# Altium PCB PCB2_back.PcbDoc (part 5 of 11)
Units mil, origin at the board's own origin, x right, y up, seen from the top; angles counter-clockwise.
Board outline 6299 x 3937 mil, 4 copper layers (TopLayer, GROUND, VCC, BottomLayer); 290 components, 470 nets, 2252 pads, 825 vias.
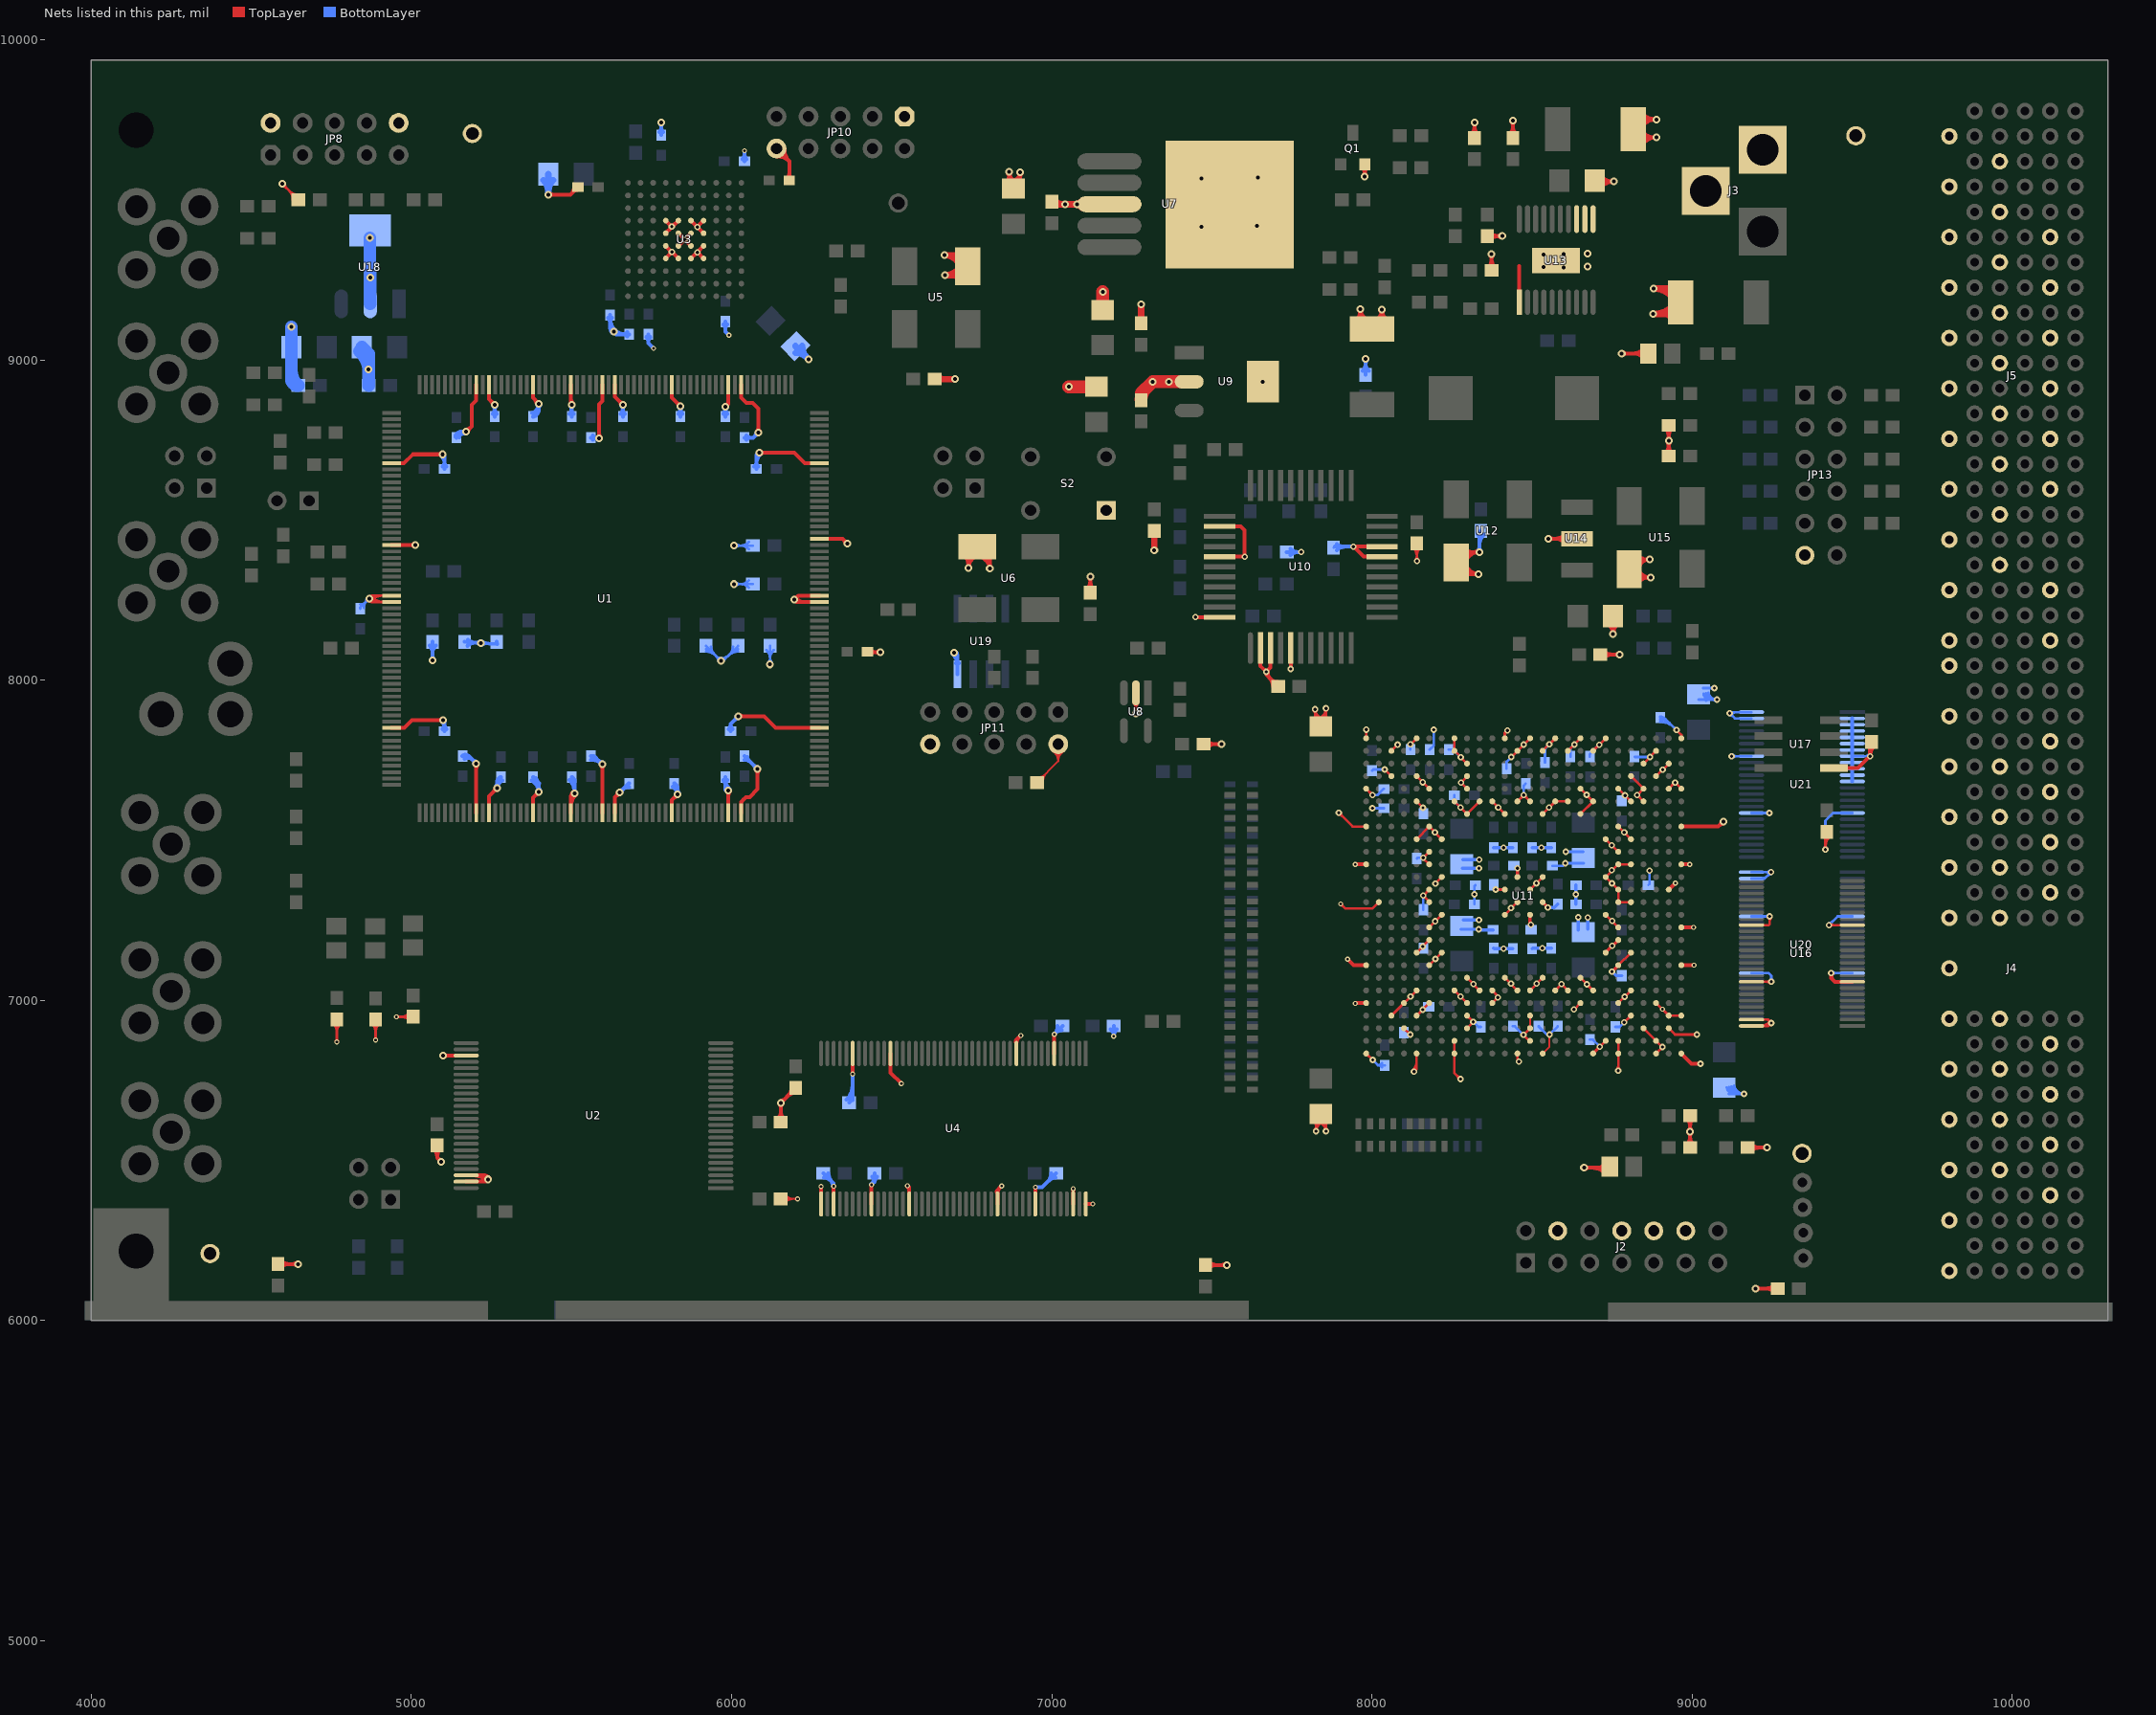
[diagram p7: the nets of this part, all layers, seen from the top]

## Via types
v1: diameter 16, hole 8, TopLayer to BottomLayer, 408 vias
v2: diameter 20, hole 10, TopLayer to BottomLayer, 221 vias
v3: diameter 24, hole 12, TopLayer to BottomLayer, 194 vias
v4: diameter 56.69, hole 56.69, TopLayer to BottomLayer, 2 vias

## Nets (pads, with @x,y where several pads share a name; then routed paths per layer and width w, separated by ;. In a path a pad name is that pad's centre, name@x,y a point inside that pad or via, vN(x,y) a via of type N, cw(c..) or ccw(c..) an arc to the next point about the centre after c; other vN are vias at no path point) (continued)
GND: C5.1 C6.1 C7.2 C8.1 C9.1 C10.2 C11.1 C12.2 C13.2 C14.2 C15.1 C16.1 C17.1 C18.1 C19.1 C20.2 C21.2 C22.1 C23.2 C27.1 C28.1 C29.2 C30.2 C31.2 C32.1 C33.1 C34.1 C35.2 C36.1 C37.1 C38.2 C39.1 C40.2 C41.1 C42.1 C43.2 C44.2 C45.2 C46.1 C47.2 C48.2 C49.2 C50.2 C51.2 C52.2 C53.2 C54.2 C55.2 C56.2 C57.2 C58.2 C59.1 C60.2 C61.2 C62.1 C63.2 C64.2 C65.1 C66.1 C67.2 C68.1 C69.2 C70.1 C71.2 C72.2 C73.2 C74.1 C75.2 C76.1 C77.2 C78.2 C79.1 C80.1 C81.1 C82.1 C83.1 C84.1 C86.1 C89.1 C91.2 C92.1 C93.2 C94.2 C95.2 C96.2 C97.2 C98.2 C99.2 C100.2 C101.2 C102.2 C103.2 C104.2 C105.1 C106.2 C107.2 C108.2 C109.2 C110.2 C111.2 C112.1 C113.2 C114.2 C115.2 C116.2 C117.1 C119.2 C120.2 C121.2 C122.2 C123.2 C124.2 C125.2 C126.2 C127.2 C128.2 C129.2 C130.1 C131.2 C132.2 C133.2 C134.2 C135.2 C136.2 C137.2 C138.2 C139.2 C140.2 C141.2 C142.2 C143.2 C144.2 C145.2 C146.2 C147.2 DS4.2 DS5.2 FB1.2 FB2.2 FB3.2 FB5.2 J2.4 J2.8 J2.10 J2.12 J3.2 J3.3 J4.B4 J4.B6 J4.B8 J4.B10 J4.B16 J4.B18 J4.B20 J4.B22 J4.D5 J4.D7 J4.D9 J4.D11 J4.D15 J4.D17 J4.D19 J4.D21 J4.F1 J4.F3 J4.F5 J4.F7 J4.F9 J4.F11 J4.F13 J4.F15 J4.F17 J4.F19 J4.F21 J4.F23 J4.F25 J5.B1 J5.B3 J5.B7 J5.B9 J5.B11 J5.B13 J5.B15 J5.B17 J5.D4 J5.D6 J5.D8 J5.D10 J5.D12 J5.D14 J5.D16 J5.D18 J5.D20 J5.F1 J5.F3 J5.F5 J5.F7 J5.F9 J5.F11 J5.F13 J5.F15 J5.F17 J5.F19 J5.F21 JP8.2 JP8.10 JP10.1 JP10.10 JP11.2 JP11.10 JP13.11 pad.5 pad.6 pad.7 pad.8 Q1.3 R4.2 R14.1 R16.2 R17.2 R20.1 R25.1 R43.2 R48.1 R50.1 R52.1 R53.1 R55.1 R67.1 R68.1 S2.1 U1.10 U1.30 U1.31 U1.40 U1.52 U1.69 U1.71 U1.80 U1.89 U1.91 U1.96 U1.102 U1.109 U1.111 U1.129 U1.142 U1.150 U1.151 U1.171 U1.190 U1.192 U1.199 U1.205 U1.210 U1.212 U1.221 U1.230 U1.232 U2.27 U2.46 U2.47 U3.D4 U3.D5 U3.D6 U3.D7 U3.E4 U3.E5 U3.E6 U3.E7 U3.F4 U3.F5 U3.F6 U3.F7 U3.G4 U3.G5 U3.G6 U3.G7 U4.6 U4.12 U4.32 U4.38 U4.44 U4.46 U4.52 U4.58 U4.72 U4.78 U4.84 U4.86 U5.2 U6.2 U7.3 U8.2 U9.2 U9.4 U10.2 U10.3 U10.5 U10.18 U10.19 U10.35 U10.38 U10.44 U11.A1 U11.A3 U11.A6 U11.A8 U11.A12 U11.A14 U11.A19 U11.A22 U11.A26 U11.AA4 U11.AA5 U11.AA8 U11.AA10 U11.AA11 U11.AA13 U11.AA14 U11.AA16 U11.AA17 U11.AA19 U11.AA22 U11.AB1 U11.AB2 U11.AB4 U11.AB6 U11.AB9 U11.AB18 U11.AB21 U11.AB26 U11.AC3 U11.AC5 U11.AC18 U11.AC22 U11.AC24 U11.AD2 U11.AD4 U11.AD18 U11.AE3 U11.AE8 U11.AE10 U11.AE12 U11.AE14 U11.AE19 U11.AE24 U11.AF1 U11.AF7 U11.AF9 U11.AF11 U11.AF13 U11.AF15 U11.AF19 U11.AF22 U11.AF26 U11.B3 U11.B6 U11.B7 U11.B13 U11.B19 U11.C2 U11.C4 U11.C13 U11.C18 U11.C23 U11.D1 U11.D2 U11.D5 U11.D13 U11.D18 U11.D22 U11.D24 U11.E3 U11.E6 U11.E9 U11.E16 U11.E18 U11.E21 U11.E23 U11.E26 U11.F5 U11.F8 U11.F10 U11.F11 U11.F13 U11.F14 U11.F16 U11.F17 U11.F19 U11.F22 U11.G9 U11.G12 U11.G15 U11.G18 U11.H1 U11.H6 U11.H21 U11.H26 U11.J5 U11.J7 U11.J20 U11.J22 U11.K6 U11.K21 U11.L1 U11.L6 U11.L21 U11.M7 U11.M13 U11.M15 U11.M20 U11.N5 U11.N6 U11.N12 U11.N14 U11.N21 U11.N25 U11.P2 U11.P6 U11.P13 U11.P15 U11.P21 U11.R7 U11.R12 U11.R14 U11.R20 U11.T1 U11.T5 U11.T6 U11.T21 U11.T26 U11.U6 U11.U21 U11.V5 U11.V7 U11.V20 U11.V22 U11.W1 U11.W6 U11.W21 U11.W26 U11.Y9 U11.Y12 U11.Y15 U11.Y18 U12.2 U13.1 U13.11 U13.12 U13.13 U14.2 U15.2 U16.8 U16.17 U16.32 U16.41 U16.47 U16.48 U17.5 U18.2 U18.4 U19.4 U20.8 U20.17 U20.32 U20.41 U20.47 U20.48 U21.2 U21.3 U21.4 U21.5 U21.6 U21.7 U21.8 U21.9 U21.10 U21.11 U21.12 U21.17 U21.32 U21.41 U21.47 U21.48 | length 33831
  TopLayer w6: R20.1@6153.46,6380 v1(6206,6380) ; R20.1@6162.99,6372.44 cw(c6181.23,6354.2) 6181.23,6380 cw(c6181.23,6405.8) R20.1@6162.99,6387.56 ; R20.1@6167.23,6368.2 cw(c6195.71,6339.72) 6195.71,6380 cw(c6195.71,6420.28) R20.1@6167.23,6391.8 ; v1@6202.46,6376.46 ccw(c6193.93,6367.93) 6193.93,6380 ccw(c6193.93,6392.07) v1@6202.46,6383.54 ; R25.1@6953.46,7680 7020,7746.54 ; R25.1@6955.43,7690.69 ccw(c6955.43,7711.73) R25.1@6970.31,7696.85 ; R25.1@6955.43,7696.69 ccw(c6955.43,7732.21) 6980.56,7707.09 ; R25.1@6966.12,7680 cw(c6996.67,7680) 6975.07,7701.6 ; R25.1@6972.12,7680 cw(c7017.15,7680) 6985.31,7711.84 ; JP11.2@7004.05,7776.98 cw(c6982.96,7746.54) 7020,7746.54 ; JP11.2@7007.47,7781.92 cw(c6990.9,7757.99) 7020,7757.99 cw(c7049.1,7757.99) JP11.2@7032.53,7781.92 ; JP11.2@7020,7800 7020,7746.54 ; JP11.2@7035.95,7776.98 ccw(c7057.04,7746.54) 7020,7746.54 ; U11.C13@8493.56,6912.74 U11.D13@8493.56,6952.11 ; U11.A12@8532.93,6834 8553.99,6855.06 v2(8553.99,6893)
  TopLayer w8: v3@4596.54,9542 cw(c4596.54,9522.69) 4610.19,9536.34 cw(c4623.85,9550) v3@4604.54,9550 ; v3(4596.54,9550) R14.1@4646.54,9500 ; 4616.4,9530.14 cw(c4586.26,9500) R14.1@4628.88,9500 ; 4621.15,9525.38 ccw(c4644.57,9548.8) R14.1@4644.57,9515.68 ; R14.1@4630.06,9516.48 cw(c4613.58,9500) R14.1@4636.88,9500 ; R4.2@4755.91,6927.48 cw(c4729.13,6900.7) 4767,6900.7 cw(c4804.87,6900.7) R4.2@4778.09,6927.48 ; v1@4764.17,6872.83 ccw(c4757.34,6879.66) 4767,6879.66 ccw(c4776.66,6879.66) v1@4769.83,6872.83 ; v1(4767,6870) R4.2@4767,6940.54 ; v3@4862.34,8249.34 ccw(c4874.86,8261.86) 4874.86,8244.16 ; v3@4869.4,8247.12 cw(c4871.28,8236.6) 4878.84,8244.16 ; v3@4870.76,8262.51 ccw(c4872.76,8267.92) 4876.84,8263.84 ; v3@4873.66,8249.34 cw(c4908.66,8214.34) U1.150@4908.66,8263.84 ; v3@4873.66,8260.66 ccw(c4913.49,8300.49) U1.151@4913.49,8244.16 ; v3@4875.51,8257.76 cw(c4880.92,8259.76) 4876.84,8263.84 ; v3@4875.88,8253.6 ccw(c4886.4,8251.72) 4878.84,8244.16 ; R16.2@4876.91,6926.48 cw(c4850.13,6899.7) 4888,6899.7 cw(c4925.87,6899.7) R16.2@4899.09,6926.48 ; v1@4885.17,6878.83 ccw(c4878.34,6885.66) 4888,6885.66 ccw(c4897.66,6885.66) v1@4890.83,6878.83 ; v1(4888,6876) R16.2@4888,6939.54 ; 4889.35,8263.84 ccw(c4889.35,8233.65) v3(4868,8255) ; 4894.18,8244.16 cw(c4894.18,8281.18) v3(4868,8255) ; U1.151@4937.69,8244.16 4878.84,8244.16 ; U1.150@4937.69,8263.84 4876.84,8263.84 ; v1(4952.54,6948.54) R17.2@5005,6948.54 ; v1@4955.36,6945.71 cw(c4962.19,6938.88) 4962.19,6948.54 cw(c4962.19,6958.19) v1@4955.36,6951.36 ; R17.2@4993.91,6937.44 ccw(c4967.13,6910.67) 4967.13,6948.54 ccw(c4967.13,6986.4) R17.2@4993.91,6959.63 ; C20.2@7816.62,6625.44 cw(c7796.39,6605.21) 7825,6605.21 ; C21.2@7816.62,7874.56 ccw(c7803.63,7887.55) 7822,7887.55 ; v2@7817.76,7904.76 cw(c7807.51,7894.51) 7822,7894.51 cw(c7836.49,7894.51) v2@7826.24,7904.76 ; v2@7820.76,6595.24 ccw(c7810.51,6605.49) 7825,6605.49 ccw(c7839.49,6605.49) v2@7829.24,6595.24 ; C21.2@7822,7855 v2(7822,7909) ccw(c7850.21,7909) C21.2@7843.05,7881.71 ; 7822,7888.25 ccw(c7844.76,7888.25) C21.2@7838.98,7866.24 ; 7822,7898.63 ccw(c7847.49,7898.63) C21.2@7841.01,7873.97 ; v2@7825,6589.88 cw(c7856.01,6589.88) C20.2@7845.44,6619.03 ; v2(7825,6591) C20.2@7825,6639 ; 7825,6601.29 cw(c7851.87,6601.29) C20.2@7842.71,6626.55 ; 7825,6612.7 cw(c7847.74,6612.7) C20.2@7839.98,6634.07 ; C21.2@7834.37,7880.9 ccw(c7822.82,7912) v2(7856,7912) C21.2@7856,7851 ; C20.2@7835.09,6618.85 cw(c7825.18,6589.67) v2@7856,6589.67 ; C21.2@7837.15,7873.4 ccw(c7827.09,7900.5) 7856,7900.5 ; C20.2@7837.67,6626.42 cw(c7828.98,6600.83) v2@7856,6600.83 ; C21.2@7839.94,7865.9 ccw(c7831.36,7888.99) 7856,7888.99 ; C20.2@7840.24,6634 cw(c7832.77,6612) 7856,6612 ; v2@7851.76,6595.24 ccw(c7841.51,6605.49) 7856,6605.49 ccw(c7870.49,6605.49) v2@7860.24,6595.24 ; v2@7851.76,7907.76 cw(c7841.51,7897.51) 7856,7897.51 cw(c7870.49,7897.51) v2@7860.24,7907.76 ; v2(7856,6591) C20.2@7856,6644 ; 7856,6607.62 cw(c7881.2,6607.62) C20.2@7863.38,6625.44 ; 7856,7892.38 ccw(c7881.2,7892.38) C21.2@7863.38,7874.56 ; v2@7896,7580 cw(c7896,7565.51) 7906.24,7575.76 cw(c7916.49,7586) v2@7902,7586 ; v2(7896,7586) 7939.34,7542.66 U11.W26@7981.75,7542.66 ; v1@7902,7297 cw(c7902,7287.34) 7908.83,7294.17 cw(c7915.66,7301) v1@7906,7301 ; v1(7902,7301) 7916,7287 8001.68,7287 U11.N25@8021.12,7306.44 ; U11.A26@7981.75,6834 v2(8002,6813.75) ; U11.AB26@7981.75,7660.77 v2(8001.52,7641) ; U11.AF26@7981.75,7818.25 v2(7981.75,7845.25) ; v2(8039.63,7721) U11.AC24@8060.49,7700.14 ; U11.D24@8060.49,6952.11 U11.F22@8139.23,7030.85 ; U11.AE24@8060.49,7778.88 v2(8080,7798.39) ; U11.C23@8099.86,6912.74 v2(8119.6,6893) ; v2(8120,7799.02) U11.AF22@8139.23,7818.25 ; v2@8126.76,6781.24 ccw(c8096.65,6811.35) 8139.23,6811.35 ; R43.2@8128.91,8413.48 cw(c8102.13,8386.7) 8140,8386.7 cw(c8177.87,8386.7) R43.2@8151.09,8413.48 ; v2(8131,6777) 8139.23,6785.23 ; v2@8132,6782.92 ccw(c8133.37,6791.08) 8139.23,6785.23 ; v2@8132.41,6775.59 ccw(c8115.96,6792.04) 8139.23,6792.04 ; v2@8135.76,8376.24 ccw(c8125.51,8386.49) 8140,8386.49 ccw(c8154.49,8386.49) v2@8144.24,8376.24 ; v2@8136.92,6778 cw(c8145.08,6779.37) 8139.23,6785.23 ; U11.A22@8139.23,6834 8139.23,6785.23 ; U11.D22@8139.23,6952.11 U11.E21@8178.6,6991.48 ; U11.J22@8139.23,7148.96 U11.K21@8178.6,7188.33 ; U11.V22@8139.23,7503.29 U11.W21@8178.6,7542.66 U11.V20@8217.97,7503.29 ; U11.AA22@8139.23,7621.4 v2(8159,7601.63) ; U11.AC22@8139.23,7700.14 U11.AB21@8178.6,7660.77 ; v2(8140,8372) R43.2@8140,8426.54 ; U11.H21@8178.6,7109.59 U11.J20@8217.97,7148.96 ; U11.L21@8178.6,7227.7 U11.M20@8217.97,7267.07 ; U11.N21@8178.6,7306.44 8178.6,7308.4 v2(8160,7327) 8178.6,7345.6 U11.P21@8178.6,7345.81 ; U11.T21@8178.6,7424.55 8159.68,7443.47 v2(8159.68,7445) U11.U21@8178.6,7463.92 ; v2(8197.79,7365) U11.R20@8217.97,7385.18 ; U11.B19@8257.34,6873.37 8257.34,6772.66 v2(8276,6754) ; U11.F19@8257.34,7030.85 U11.E18@8296.71,6991.48 ; U11.AA19@8257.34,7621.4 U11.Y18@8296.71,7582.03 U11.AA17@8336.08,7621.4 ; U11.AF19@8257.34,7818.25 U11.AE19@8257.34,7778.88 U11.AD18@8296.71,7739.51 ; v2@8270,6754 ccw(c8255.51,6754) 8265.76,6764.24 ccw(c8276,6774.49) v2@8276,6760 ; U11.C18@8296.71,6912.74 8316,6932.03 v2(8316,6932.82) U11.D18@8296.71,6952.11 ; U11.G18@8296.71,7070.22 U11.F17@8336.08,7030.85 ; U11.AB18@8296.71,7660.77 8278,7679.48 v2(8278,7680) 8296.71,7698.71 U11.AC18@8296.71,7700.14 ; U11.E16@8375.45,6991.48 v2(8393,7009.03) 8393,7013.3 U11.F16@8375.45,7030.85 ; U11.AA16@8375.45,7621.4 U11.Y15@8414.82,7582.03 ; U11.G15@8414.82,7070.22 U11.F14@8454.19,7030.85 ; U11.M15@8414.82,7267.07 U11.N14@8454.19,7306.44 ; U11.AF15@8414.82,7818.25 8414.82,7834.82 v2(8423,7843) ; v2(8435,7759.69) v2(8473.88,7798.58) U11.AF13@8493.56,7818.25 ; U11.A14@8454.19,6834 8454.19,6813.81 v2(8459,6809) ; U11.AA14@8454.19,7621.4 v2(8473.79,7641) 8473.96,7641 U11.AA13@8493.56,7621.4 ; U11.B13@8493.56,6873.37 8491.45,6873.37 v2(8472.82,6892) U11.C13@8493.56,6912.74 ; U11.F13@8493.56,7030.85 U11.G12@8532.93,7070.22 ; U11.P13@8493.56,7345.81 U11.R12@8532.93,7385.18 ; U11.Y12@8532.93,7582.03 U11.AA11@8572.3,7621.4 U11.AA10@8611.67,7621.4 ; U11.AE12@8532.93,7778.88 U11.AF11@8572.3,7818.25 ; U11.F11@8572.3,7030.85 8591.52,7050.07 v2(8591.52,7051) U11.F10@8611.67,7030.85 ; U11.AE10@8611.67,7778.88 U11.AF9@8651.04,7818.25 ; v2(8631,6971.44) U11.E9@8651.04,6991.48 ; U11.G9@8651.04,7070.22 U11.F8@8690.41,7030.85 ; U11.Y9@8651.04,7582.03 U11.AA8@8690.41,7621.4 U11.AB9@8651.04,7660.77 ; U11.A8@8690.41,6834 U11.B7@8729.78,6873.37 ; U11.AE8@8690.41,7778.88 U11.AF7@8729.78,7818.25 ; U11.M7@8729.78,7267.07 U11.L6@8769.15,7227.7 ; U11.V7@8729.78,7503.29 U11.U6@8769.15,7463.92 ; v2@8764.76,6784.24 ccw(c8754.15,6794.85) 8769.15,6794.85 ; v2(8769,6780) 8769.15,6780.15 U11.B6@8769.15,6873.37 ; 8769.15,6794.12 ccw(c8783.12,6794.12) v2@8773.24,6784.24 ; U11.E6@8769.15,6991.48 U11.F5@8808.52,7030.85 ; U11.H6@8769.15,7109.59 U11.J5@8808.52,7148.96 ; U11.W6@8769.15,7542.66 U11.V5@8808.52,7503.29 ; U11.AB6@8769.15,7660.77 U11.AA5@8808.52,7621.4 ; v2(8787.41,6931) U11.D5@8808.52,6952.11 ; U11.N5@8808.52,7306.44 U11.N6@8769.15,7306.44 U11.P6@8769.15,7345.81 U11.R7@8729.78,7385.18 U11.T6@8769.15,7424.55 U11.T5@8808.52,7424.55 ; U11.AC5@8808.52,7700.14 U11.AB4@8847.89,7660.77 v2(8828.12,7641) 8828,7641 8847.6,7621.4 U11.AA4@8847.89,7621.4 ; U11.C4@8847.89,6912.74 8906.63,6854 v2(8907.26,6854) U11.A3@8887.26,6834 ; U11.AD4@8847.89,7739.51 U11.AE3@8887.26,7778.88 ; U11.E3@8887.26,6991.48 U11.D2@8926.63,6952.11 U11.D1@8966,6952.11 ; U11.AC3@8887.26,7700.14 U11.AD2@8926.63,7739.51 ; U11.C2@8926.63,6912.74 8946.37,6893 v2(9015,6893) ; U11.AB2@8926.63,7660.77 8945.86,7680 v2(8946.77,7680) U11.AB1@8966,7660.77 ; v2(8951,7844) 8966,7829 U11.AF1@8966,7818.25 ; v2@9010.76,6888.76 ccw(c9000.51,6878.51) 9000.51,6893 ccw(c9000.51,6907.49) v2@9010.76,6897.24 ; U16.48@9185.04,6920 9238,6920 ; U16.47@9185.04,6939.69 9236.32,6939.69 v2(9247,6929) 9238,6920 ; U16.41@9185.04,7057.8 v2(9247.2,7057.8) ; U16.32@9185.04,7234.96 9238.96,7234.96 9242.2,7238.2 v2(9242.2,7262.2) ; U16.48@9210.79,6920 ccw(c9210.79,6965.21) v2@9242.76,6933.24 ; 9230.1,6920 ccw(c9230.1,6945.9) v2@9248.41,6927.59 ; v2@9237.96,7257.96 cw(c9227.72,7247.72) 9242.2,7247.72 cw(c9256.69,7247.72) v2@9246.45,7257.96 ; v2@9241,6929 ccw(c9226.51,6929) 9236.76,6939.24 ccw(c9247,6949.49) v2@9247,6935 ; v2@9241.03,6928.43 cw(c9230.58,6927.42) 9238,6920 ; v2@9242.96,7053.55 ccw(c9232.72,7043.31) 9232.72,7057.8 ccw(c9232.72,7072.28) v2@9242.96,7062.04 ; v2@9246.43,6923.03 ccw(c9245.42,6912.58) 9238,6920 ; C36.1@9408.91,7513.48 cw(c9391.79,7496.36) 9416,7496.36 cw(c9448.21,7496.36) C36.1@9425.43,7519.13 ; v2@9411.76,7475.24 ccw(c9401.51,7485.49) 9416,7485.49 ccw(c9430.49,7485.49) v2@9420.24,7475.24 ; v2(9416,7471) 9416,7522.54 C36.1@9420,7526.54 ; v2@9416,7477.04 cw(c9467.52,7477.04) C36.1@9431.09,7513.48 ; v2(9427.04,7234.96) U16.17@9500,7234.96 ; v2@9431.28,7230.72 cw(c9441.53,7220.47) 9441.53,7234.96 cw(c9441.53,7249.45) v2@9431.28,7239.2 ; v3(4868,8255) 4876.84,8263.84 ; v3(4868,8255) 4878.84,8244.16
  TopLayer w10: v2(8386.19,7345.81) U11.P15@8414.82,7345.81 ; U11.R14@8454.19,7385.18 v2(8454.19,7412.19) ; U11.M13@8493.56,7267.07 8493.56,7238.44 v2(8496,7236) ; U11.N12@8532.93,7306.44 v2(8549.37,7290) ; U11.J7@8729.78,7148.96 U11.K6@8769.15,7188.33 ; v2(8749.56,7090) U11.H6@8769.15,7109.59
  TopLayer w12: FB1.2@4583,6176.46 v3(4645.46,6176.46) ; FB1.2@4592.68,6166.79 cw(c4616.04,6143.43) 4616.04,6176.46 cw(c4616.04,6209.5) FB1.2@4592.68,6186.14 ; v3@4641.22,6172.22 ccw(c4630.98,6161.98) 4630.98,6176.46 ccw(c4630.98,6190.95) v3@4641.22,6180.71 ; U1.171@4937.69,7850.46 4977.46,7850.46 5002,7875 v3(5099,7875) ; U1.142@4937.69,8421.32 v3(5012.32,8421.32) ; U1.129@4937.69,8677.23 4976.23,8677.23 5004,8705 v3(5097,8705) ; v3@5008.08,8417.08 ccw(c4997.84,8406.84) 4997.84,8421.32 ccw(c4997.84,8435.81) v3@5008.08,8425.57 ; C5.1@5070.32,6534.89 cw(c5046.96,6511.53) 5080,6511.53 cw(c5113.04,6511.53) C5.1@5089.68,6534.89 ; C5.1@5080,6546.54 5080,6509 v3(5093,6496) ; v3@5087,6496 ccw(c5072.51,6496) 5082.76,6506.24 ccw(c5093,6516.49) v3@5093,6502 ; v3@5092.76,8700.76 ccw(c5082.51,8690.51) 5082.51,8705 ccw(c5082.51,8719.49) v3@5092.76,8709.24 ; v3@5094.76,7870.76 ccw(c5084.51,7860.51) 5084.51,7875 ccw(c5084.51,7889.49) v3@5094.76,7879.24 ; v3(5098,6827) U2.27@5170.72,6827.39 ; v3@5102.22,6831.27 ccw(c5112.41,6841.56) 5112.49,6827.08 ccw(c5112.56,6812.59) v3@5102.27,6822.78 ; U2.47@5170.72,6433.69 5231.69,6433.69 v3(5239,6441) 5226.63,6453.37 U2.46@5170.72,6453.37 ; v3(5171,8776) 5188,8793 5188,8859 5202.46,8873.46 U1.111@5202.46,8922.31 ; v3@5171,8782 ccw(c5171,8796.49) 5181.24,8786.24 ccw(c5191.49,8776) v3@5177,8776 ; U2.46@5194.65,6453.37 cw(c5194.65,6396.65) v3@5234.76,6436.76 ; v3@5198.21,7735.3 cw(c5187.97,7725.06) 5202.46,7725.06 cw(c5216.94,7725.06) v3@5206.7,7735.3 ; U1.190@5202.46,7585.69 v3(5202.46,7739.54) ; U2.47@5206.85,6433.69 ccw(c5206.85,6473.15) v3@5234.76,6445.24 ; 5223.62,6453.37 cw(c5223.62,6425.62) v3@5243.24,6445.24 ; v3@5233,6441 ccw(c5218.51,6441) 5228.76,6451.24 ccw(c5239,6461.49) v3@5239,6447 ; U1.192@5241.83,7585.69 5241.83,7637.83 v3(5267,7663) ; U1.109@5241.83,8922.31 5241.83,8877.17 v3(5260,8859) ; v3@5254,8859 ccw(c5239.51,8859) 5249.76,8869.24 ccw(c5260,8879.49) v3@5260,8865 ; v3@5261,7663 cw(c5246.51,7663) 5256.76,7652.76 cw(c5267,7642.51) v3@5267,7657 ; U1.199@5379.62,7585.69 5379.62,7632.62 v3(5398,7651) ; U1.102@5379.62,8922.31 5379.62,8881.38 v3@5398,8863 ; 5385.34,8875.66 cw(c5371.69,8862) v3@5391,8862 ; v3@5392,7651 cw(c5377.51,7651) 5387.76,7640.76 cw(c5398,7630.51) v3@5398,7645 ; v3(5427.2,9516.2) 5496.2,9516.2 C6.1@5520,9540 ; v3@5431.44,9511.95 cw(c5441.68,9501.71) 5441.68,9516.2 cw(c5441.68,9530.68) v3@5431.44,9520.44 ; U1.205@5497.73,7585.69 5497.73,7634.73 v3(5509,7646) ; U1.205@5497.73,7604.31 cw(c5550.69,7604.31) v3@5513.24,7641.76 ; 5497.73,7633.28 cw(c5521.72,7633.28) v3@5504.76,7650.24 ; 5497.73,8879.96 ccw(c5519.96,8879.96) v3@5504.24,8864.24 ; U1.96@5497.73,8922.31 5497.73,8862.27 v3(5500,8860) ; 5500.37,9520.37 ccw(c5480.74,9540) C6.1@5508.5,9540 ; v3@5503,7646 cw(c5488.51,7646) 5498.76,7635.76 cw(c5509,7625.51) v3@5509,7640 ; C6.1@5506.4,9526.4 cw(c5517.5,9515.31) C6.1@5517.5,9531 ; v3@5581.76,8759.24 ccw(c5571.51,8769.49) 5586,8769.49 ccw(c5600.49,8769.49) v3@5590.24,8759.24 ; v3(5586,8755) 5586,8861 5596.16,8871.16 U1.91@5596.16,8922.31 ; v3@5591.91,7732.6 cw(c5581.67,7722.36) 5596.16,7722.36 cw(c5610.64,7722.36) v3@5600.4,7732.6 ; U1.210@5596.16,7585.69 v3(5596.16,7736.84) ; U1.212@5635.53,7585.69 5635.53,7634.53 v3(5650,7649) ; U1.89@5635.53,8922.31 5635.53,8884.47 v3(5660,8860) ; v3@5644,7649 cw(c5629.51,7649) 5639.76,7638.76 cw(c5650,7628.51) v3@5650,7643 ; v3@5654,8860 ccw(c5639.51,8860) 5649.76,8870.24 ccw(c5660,8880.49) v3@5660,8866 ; U3.G4@5794.11,9316.78 5813.73,9336.4 v2@5813.73,9336.53 ; U3.F4@5794.11,9356.15 U3.G5@5833.48,9316.78 ; U3.E4@5794.11,9395.52 5813.8,9415.2 U3.D5@5833.48,9434.89 ; U3.D4@5794.11,9434.89 v2(5813.05,9415.95) ; 5805.16,9406.57 ccw(c5795.78,9415.95) v2@5809.05,9415.95 ; 5805.53,9328.19 ccw(c5796.66,9337.06) v2@5809.2,9337.06 ; U1.221@5812.69,7585.69 5812.69,7624.69 v3(5831,7643) ; U1.80@5812.69,8922.31 5812.69,8882.31 v3(5840,8855) ; v2@5813.05,9419.95 ccw(c5813.05,9433.22) 5822.43,9423.84 ; v3@5825,7643 cw(c5810.51,7643) 5820.76,7632.76 cw(c5831,7622.51) v3@5831,7637 ; U3.F5@5833.48,9356.15 U3.E6@5872.85,9395.52 ; U3.E5@5833.48,9395.52 v2(5853.17,9375.83) U3.F6@5872.85,9356.15 ; v3@5834,8855 ccw(c5819.51,8855) 5829.76,8865.24 ccw(c5840,8875.49) v3@5840,8861 ; U3.G6@5872.85,9316.78 v2@5892.05,9335.98 ; U3.D6@5872.85,9434.89 U3.E7@5912.22,9395.52 ; 5884.53,9328.46 cw(c5893.02,9319.96) v2@5893.02,9331.98 ; v2(5892.47,9415.27) 5892.6,9415.27 U3.D7@5912.22,9434.89 ; v2@5897.02,9335.98 cw(c5909.04,9335.98) 5900.54,9344.47 ; U3.G7@5912.22,9316.78 v2(5893.02,9335.98) v2@5892.05,9335.98 ; U3.F7@5912.22,9356.15 v2@5892.05,9335.98 ; v3(5980,8854) 5989.86,8863.86 ; v3@5980.16,8860 ccw(c5980.53,8873.19) 5989.86,8863.86 ; v3@5985.62,7650.9 cw(c5975.37,7640.66) 5989.86,7640.66 cw(c6004.34,7640.66) v3@5994.1,7650.9 ; v3@5986,8854.16 cw(c5999.19,8854.53) 5989.86,8863.86 ; U1.230@5989.86,7585.69 v3(5989.86,7655.14) ; U1.71@5989.86,8922.31 5989.86,8863.86 ; v3(6021,7887) 6101,7887 6137.54,7850.46 U1.10@6274.31,7850.46 ; v3@6025.24,7882.76 cw(c6035.49,7872.51) 6035.49,7887 cw(c6035.49,7901.49) v3@6025.24,7891.24 ; U1.232@6029.13,7609.31 cw(c6052.84,7609.31) 6036.08,7626.08 ; U1.232@6029.23,7585.69 6029.23,7619.23 6045,7635 6057,7635 6081,7659 v3(6081,7721.99) ; U1.69@6029.23,8922.31 6029.23,8882.77 6046,8866 6065,8866 6083,8848 v3(6083,8773) ; v3@6076.76,7717.75 cw(c6066.51,7707.51) 6081,7707.51 cw(c6095.49,7707.51) v3@6085.24,7717.75 ; v3@6078.76,8777.24 ccw(c6068.51,8787.49) 6083,8787.49 ccw(c6097.49,8787.49) v3@6087.24,8777.24 ; v3(6086,8710) 6196,8710 6228.77,8677.23 U1.52@6274.31,8677.23 ; v3@6090.24,8705.76 cw(c6100.49,8695.51) 6100.49,8710 cw(c6100.49,8724.49) v3@6090.24,8714.24 ; JP10.10@6140,9660 6180,9620 ; JP10.10@6141.17,9635.03 cw(c6143.59,9583.59) 6180,9620 ; C7.2@6143.79,6629.68 ccw(c6120.43,6653.04) 6153.46,6653.04 ccw(c6186.5,6653.04) C7.2@6163.14,6629.68 ; v3@6149.22,6675.76 cw(c6138.98,6665.51) 6153.46,6665.51 cw(c6167.95,6665.51) v3@6157.71,6675.76 ; C7.2@6153.46,6620 v3(6153.46,6680) C8.1@6200,6726.54 ; v3@6153.46,6686 ccw(c6153.46,6700.49) 6163.71,6690.24 ccw(c6173.95,6680) v3@6159.46,6680 ; JP10.10@6164.97,9658.83 ccw(c6216.41,9656.41) 6180,9620 ; 6173.28,6699.81 cw(c6200,6673.09) C8.1@6200,6710.88 ; C9.1@6173.64,9566.36 ccw(c6158.27,9581.73) 6180,9581.73 ccw(c6201.73,9581.73) C9.1@6186.36,9566.36 ; 6178.03,6704.57 ccw(c6158.03,6724.57) C8.1@6186.32,6724.57 ; C9.1@6180,9560 6180,9620 ; v3@6196,8257 ccw(c6196,8271.49) 6206.24,8261.24 ccw(c6216.49,8251) v3@6202,8251 ; v3@6200.24,8255.24 ccw(c6227,8282) 6227,8244.16 ; U1.30@6274.31,8244.16 6202.84,8244.16 v3(6196,8251) 6208.84,8263.84 U1.31@6274.31,8263.84 ; U1.40@6274.31,8441.01 6345.99,8441.01 v3(6361,8426) ; U4.44@6279.23,6364 v1(6279.23,6418.23) ; U4.46@6318.6,6364 v1(6318.6,6419.4) ; v3@6355,8426 ccw(c6340.51,8426) 6350.76,8436.24 ccw(c6361,8446.49) v3@6361,8432 ; v1(6377.65,6769.35) U4.38@6377.65,6834 ; C10.2@6422,8087.01 v3(6463.99,8087.01) ; C10.2@6432.86,8081.64 cw(c6445.83,8068.67) 6445.83,8087.01 ; C10.2@6432.86,8094.36 ccw(c6450.61,8112.12) 6450.61,8087.01 ; U4.52@6436.71,6364 v1(6436.71,6423.71) ; v3@6459.75,8082.77 ccw(c6449.51,8072.52) 6449.51,8087.01 ccw(c6449.51,8101.49) v3@6459.75,8091.25 ; U4.32@6495.77,6834 6495.77,6774.23 v1(6530,6740) ; v1@6547.59,6419.59 cw(c6530.12,6402.12) U4.58@6554.82,6402.12 ; v1@6548.9,6419 cw(c6548.58,6412.77) 6554.82,6412.77 ; v1(6549,6421) 6554.82,6415.18 U4.58@6554.82,6364 ; U6.2@6723.72,8393.25 cw(c6684.41,8353.95) v3@6740,8353.95 ; v3@6735.76,8354.24 ccw(c6725.51,8364.49) 6740,8364.49 ccw(c6754.49,8364.49) v3@6744.24,8354.24 ; v3@6740,8349.6 cw(c6782.55,8349.6) U6.2@6762.8,8387.29 ; v3(6740,8350) U6.2@6740,8416 ; 6740,8369.44 cw(c6772.16,8369.44) U6.2@6757.23,8397.92 ; U6.2@6776.8,8384.98 cw(c6764.5,8345.34) v3@6806,8345.34 ; U6.2@6780.35,8396.44 cw(c6769.55,8361.63) 6806,8361.63 ; U6.2@6783.91,8407.9 cw(c6774.61,8377.92) U6.2@6806,8377.92 ; v3@6801.76,8352.24 ccw(c6791.51,8362.49) 6806,8362.49 ccw(c6820.49,8362.49) v3@6810.24,8352.24 ; v3(6806,8348) U6.2@6806,8409 ; U4.72@6830.32,6397.46 cw(c6854.1,6397.46) 6837.28,6414.28 ; U4.72@6830.34,6397.4 cw(c6835.45,6402.37) 6830.41,6407.41 ; U4.72@6830.41,6364 6830.41,6407.41 ; v1(6843,6420) 6830.41,6407.41 ; C12.2@6858.03,9553.15 ccw(c6838.8,9572.38) 6866,9572.38 ; v3@6861.76,9582.76 cw(c6851.51,9572.51) 6866,9572.51 cw(c6880.49,9572.51) v3@6870.24,9582.76 ; C12.2@6866,9536 v3(6866,9587) ccw(c6896.13,9587) C12.2@6885.26,9558.9 ; 6866,9569.49 ccw(c6889.36,9569.49) C12.2@6880.93,9547.71 ; C12.2@6879.43,9560.21 ccw(c6874.8,9586) v3(6901,9586) C12.2@6901,9531 ; C12.2@6881.55,9548.4 ccw(c6877.38,9571.65) 6901,9571.65 ; U4.12@6889.37,6867.46 cw(c6910.87,6867.46) 6895.67,6882.67 ; U4.12@6889.4,6867.4 cw(c6894.03,6871.9) 6889.46,6876.46 ; U4.12@6889.47,6834 6889.47,6876.47 ; v3@6896.76,9581.76 cw(c6886.51,9571.51) 6901,9571.51 cw(c6915.49,9571.51) v3@6905.24,9581.76 ; v1(6903,6890) 6889.47,6876.47 ; U4.78@6948.52,6364 v1(6948.52,6416.52) ; U4.6@7007.57,6834 v1(7007.57,6894.11) ; U4.84@7066.63,6364 v1(7066.63,6411.63) ; U4.86@7106,6364 v1(7128,6364) ; C16.1@7110.32,8285.11 ccw(c7086.96,8308.47) 7120,8308.47 ccw(c7153.04,8308.47) C16.1@7129.68,8285.11 ; v3@7115.76,8318.76 cw(c7105.51,8308.51) 7120,8308.51 cw(c7134.49,8308.51) v3@7124.24,8318.76 ; C16.1@7120,8273.46 v3(7120,8323) ; v3@7258.36,7899.64 ccw(c7248.11,7909.89) 7262.6,7909.89 ccw(c7277.08,7909.89) v3@7266.84,7899.64 ; U8.2@7258.49,7928.33 cw(c7248.57,7918.41) 7262.6,7918.41 cw(c7276.63,7918.41) U8.2@7266.71,7928.33 ; v3(7262.6,7895.4) U8.2@7262.6,7960 ; v2(7448.54,8196.46) U10.44@7523.54,8196.46 ; C19.1@7473.46,7800 v3(7530,7800) ; FB3.2@7480,6173.46 v3(7546.46,6173.46) ; C19.1@7485.11,7790.32 cw(c7508.47,7766.96) 7508.47,7800 cw(c7508.47,7833.04) C19.1@7485.11,7809.68 ; FB3.2@7489.68,6163.79 cw(c7513.04,6140.43) 7513.04,6173.46 cw(c7513.04,6206.5) FB3.2@7489.68,6183.14 ; U10.38@7523.54,8385.43 v2(7602.43,8385.43) 7602.43,8467.57 7590.08,8479.92 U10.35@7523.54,8479.92 ; v3@7525.76,7795.76 ccw(c7515.51,7785.51) 7515.51,7800 ccw(c7515.51,7814.49) v3@7525.76,7804.24 ; v3@7542.22,6169.22 ccw(c7531.98,6158.98) 7531.98,6173.46 ccw(c7531.98,6187.95) v3@7542.22,6177.71 ; U10.2@7651.5,8100 7651.5,8044.5 v2(7670,8026) ; v2@7674,8026 ccw(c7706.51,8026) 7683.52,8003.01 ; 7679.81,8006.72 cw(c7653.09,7980) C22.1@7690.88,7980 ; U10.3@7682.99,8100 7682.99,8038.99 v2(7670,8026) ; 7684.57,8001.97 ccw(c7704.57,8021.97) C22.1@7704.57,7993.68 ; C22.1@7706.54,7980 7670,8016.54 v2(7670,8026) ; v2(7745.98,8034.98) U10.5@7745.98,8100 ; v1(7924,7128) 7942.41,7109.59 U11.H26@7981.75,7109.59 ; v1(7947.45,7424.55) U11.T26@7981.75,7424.55 ; C23.2@7947.45,9120.38 ccw(c7910.66,9159) v3(7964,9159) ; v1(7948,6990) 7949.48,6991.48 U11.E26@7981.75,6991.48 ; v3@7959.76,9154.76 cw(c7949.51,9144.51) 7964,9144.51 cw(c7978.49,9144.51) v3@7968.24,9154.76 ; C23.2@7964,9097 v3(7964,9159) ; 7964,9140.09 ccw(c7991.11,9140.09) C23.2@7979.57,9115.56 ; Q1.3@7969.12,9601.52 cw(c7949.12,9581.52) 7977.4,9581.52 cw(c8005.69,9581.52) Q1.3@7985.69,9601.52 ; v3@7973.16,9576.84 ccw(c7962.92,9587.08) 7977.4,9587.08 ccw(c7991.89,9587.08) v3@7981.64,9576.84 ; v3(7977.4,9572.6) Q1.3@7977.4,9610.79 ; C23.2@7984.68,9126.42 cw(c8000.01,9159) v3(7964,9159) ; C23.2@8012.67,9125.02 ccw(c7993.94,9157) v3(8031,9157) ; C23.2@8018.73,9114.66 ccw(c8006.2,9136.07) 8031,9136.07 ; v3@8026.76,9152.76 cw(c8016.51,9142.51) 8031,9142.51 cw(c8045.49,9142.51) v3@8035.24,9152.76 ; C23.2@8031,9101 v3(8031,9157) ; U10.18@8031.42,8385.43 7973.43,8385.43 v2(7941.93,8416.93) U10.19@8031.42,8416.93 ; C23.2@8048.48,9123.68 cw(c8071.48,9157) v3(8031,9157) ; U12.2@8255,8331 v3(8333,8331) cw(c8333,8371.57) U12.2@8294.67,8358.26 ; U12.2@8259,8400 v3(8335,8400) ccw(c8335,8354.74) U12.2@8293.64,8373.13 ; U12.2@8272,8350.39 ccw(c8299.26,8359.85) U12.2@8299.26,8331 ; U12.2@8282.68,8378 cw(c8316.53,8362.95) 8316.53,8400 ; U12.2@8283.34,8354.32 ccw(c8316.13,8365.71) 8316.13,8331 ; U12.2@8286.75,8323.72 cw(c8304.32,8306.14) 8304.32,8331 ; U12.2@8286.75,8410.28 ccw(c8311.57,8435.1) 8311.57,8400 ; C27.1@8310.32,9705.11 ccw(c8286.96,9728.47) 8320,9728.47 ccw(c8353.04,9728.47) C27.1@8329.68,9705.11 ; v3@8315.76,9737.76 cw(c8305.51,9727.51) 8320,9727.51 cw(c8334.49,9727.51) v3@8324.24,9737.76 ; C27.1@8320,9693.46 v3(8320,9742) ; v3@8328.76,8326.76 ccw(c8318.51,8316.51) 8318.51,8331 ccw(c8318.51,8345.49) v3@8328.76,8335.24 ; v3@8330.76,8395.76 ccw(c8320.51,8385.51) 8320.51,8400 ccw(c8320.51,8414.49) v3@8330.76,8404.24 ; R50.1@8360,9386.54 v3(8406.46,9386.54) ; R48.1@8363.79,9289.68 ccw(c8340.43,9313.04) 8373.46,9313.04 ccw(c8406.5,9313.04) R48.1@8383.14,9289.68 ; v3@8369.22,9326.22 cw(c8358.98,9315.98) 8373.46,9315.98 cw(c8387.95,9315.98) v3@8377.71,9326.22 ; R50.1@8369.68,9376.86 cw(c8393.04,9353.5) 8393.04,9386.54 cw(c8393.04,9419.57) R50.1@8369.68,9396.21 ; R48.1@8373.46,9280 v3(8373.46,9330.46) ; v3@8402.22,9382.29 ccw(c8391.98,9372.05) 8391.98,9386.54 ccw(c8391.98,9401.02) v3@8402.22,9390.78 ; C28.1@8430.32,9705.11 ccw(c8406.96,9728.47) 8440,9728.47 ccw(c8473.04,9728.47) C28.1@8449.68,9705.11 ; v3@8435.76,9742.76 cw(c8425.51,9732.51) 8440,9732.51 cw(c8454.49,9732.51) v3@8444.24,9742.76 ; C28.1@8440,9693.46 v3(8440,9747) ; U13.1@8460,9180 8460,9293 ; v3(8550.57,8441.57) U14.2@8640,8441.57 ; v3@8554.82,8437.33 cw(c8565.06,8427.09) 8565.06,8441.57 cw(c8565.06,8456.06) v3@8554.82,8445.82 ; U14.2@8601.95,8429.11 ccw(c8571.87,8399.03) 8571.87,8441.57 ccw(c8571.87,8484.12) U14.2@8601.95,8454.04 ; v3(8662,6477) DS4.2@8743.6,6478 ; v3@8666.19,6481.29 ccw(c8676.31,6491.66) 8676.48,6477.18 ccw(c8676.66,6462.69) v3@8666.29,6472.81 ; 8685.86,6477.29 cw(c8686.6,6416.71) DS4.2@8728.92,6460.07 ; C30.2@8695,9557 v3(8756,9557) ccw(c8756,9499.17) C30.2@8713.75,9538.66 ; 8704.66,6477.52 ccw(c8704.24,6511.52) DS4.2@8728.58,6487.78 ; C30.2@8704.98,9546.85 cw(c8728.36,9525) 8728.36,9557 ; C30.2@8713.15,9574.09 ccw(c8754.41,9615.35) v3@8754.41,9557 ; C32.1@8713.46,8080 v3(8774,8080) ; 8714.83,6477.65 cw(c8715.22,6446.03) DS4.2@8737.3,6468.66 ; C32.1@8725.11,8070.32 cw(c8748.47,8046.96) 8748.47,8080 cw(c8748.47,8113.04) C32.1@8725.11,8089.68 ; C29.2@8736.93,8176.11 cw(c8710.75,8143.2) v3(8752.8,8143.2) ; v3@8748.56,8147.44 ccw(c8738.32,8157.68) 8752.8,8157.68 ccw(c8767.29,8157.68) v3@8757.05,8147.44 ; v3@8751.76,9552.76 ccw(c8741.51,9542.51) 8741.51,9557 ccw(c8741.51,9571.49) v3@8751.76,9561.24 ; C29.2@8752.8,8200 v3(8752.8,8143.2) ; C29.2@8768.68,8176.11 ccw(c8794.86,8143.2) v3(8752.8,8143.2) ; v3@8769.76,8075.76 ccw(c8759.51,8065.51) 8759.51,8080 ccw(c8759.51,8094.49) v3@8769.76,8084.24 ; v3(8780,9020) DS5.2@8862.6,9020 ; v3@8784.24,9015.76 cw(c8794.49,9005.51) 8794.49,9020 cw(c8794.49,9034.49) v3@8784.24,9024.24 ; U15.2@8802,8320 v3(8870,8320) cw(c8870,8361.89) U15.2@8832.79,8342.65 ; U15.2@8813,8377 v3(8868,8377) ccw(c8868,8340.4) U15.2@8834.08,8354.15 ; C31.2@8819,9695 v3(8889,9695) ccw(c8889,9639.54) C31.2@8843.56,9671.34 ; C31.2@8819,9751 v3(8889,9751) ; U15.2@8822.13,8337.13 ccw(c8850.28,8351.69) 8850.28,8320 ; U15.2@8822.95,8358.66 cw(c8850.18,8347.62) 8850.18,8377 ; U15.2@8826.75,8303.72 cw(c8866.05,8264.41) v3@8866.05,8320 ; U15.2@8826.75,8390.28 ccw(c8858.81,8422.34) v3@8858.81,8377 ; C31.2@8831.33,9705.58 ccw(c8856.88,9731.13) 8856.88,9695 ; C31.2@8831.93,9764.01 ccw(c8861.62,9791.37) 8861.62,9751 ; C31.2@8832.87,9736.13 cw(c8863.93,9711.12) 8863.93,9751 ; C31.2@8833.73,9678.22 cw(c8865.95,9655.67) 8865.95,9695 ; C31.2@8839.82,9714.07 ccw(c8885.85,9760.1) v3@8885.85,9695 ; C31.2@8840.76,9772.14 ccw(c8889,9816.6) v3(8889,9751) ; C31.2@8842.22,9728.6 cw(c8889,9690.95) v3(8889,9751) ; DS5.2@8848.74,9006.15 ccw(c8815.3,8972.7) 8815.3,9020 ccw(c8815.3,9067.3) DS5.2@8848.74,9033.85 ; v3@8863.76,8372.76 ccw(c8853.51,8362.51) 8853.51,8377 ccw(c8853.51,8391.49) v3@8863.76,8381.24 ; v3@8865.76,8315.76 ccw(c8855.51,8305.51) 8855.51,8320 ccw(c8855.51,8334.49) v3@8865.76,8324.24 ; v3@8884.76,9690.76 ccw(c8874.51,9680.51) 8874.51,9695 ccw(c8874.51,9709.49) v3@8884.76,9699.24 ; v3@8884.76,9746.76 ccw(c8874.51,9736.51) 8874.51,9751 ccw(c8874.51,9765.49) v3@8884.76,9755.24 ; C33.1@8916.86,8709.68 ccw(c8893.5,8733.04) 8926.54,8733.04 ccw(c8959.57,8733.04) C33.1@8936.21,8709.68 ; C34.1@8916.86,8785.32 cw(c8893.5,8761.96) 8926.54,8761.96 cw(c8959.57,8761.96) C34.1@8936.21,8785.32 ; v3@8922.29,8742.76 cw(c8912.05,8732.51) 8926.54,8732.51 cw(c8941.02,8732.51) v3@8930.78,8742.76 ; v3@8922.29,8751.24 ccw(c8912.05,8761.49) 8926.54,8761.49 ccw(c8941.02,8761.49) v3@8930.78,8751.24 ; C33.1@8926.54,8695 C34.1@8926.54,8795 ; U11.P2@8926.63,7345.81 v1(8947,7366) ; U11.A1@8966,6834 8998,6802 v2(9026,6802) ; U11.H1@8966,7109.59 v1(9005.59,7109.59) ; U11.L1@8966,7227.7 v1(9004.3,7227.7) ; U11.T1@8966,7424.55 v1(8992.55,7424.55) ; U11.W1@8966,7542.66 9081.66,7542.66 v3(9097,7558) ; R52.1@8983.79,6549.68 ccw(c8960.43,6573.04) 8993.46,6573.04 ccw(c9026.5,6573.04) R52.1@9003.14,6549.68 ; R53.1@8983.79,6630.32 cw(c8960.43,6606.96) 8993.46,6606.96 cw(c9026.5,6606.96) R53.1@9003.14,6630.32 ; v3@8989.22,6585.76 cw(c8978.98,6575.51) 8993.46,6575.51 cw(c9007.95,6575.51) v3@8997.71,6585.76 ; v3@8989.22,6594.24 ccw(c8978.98,6604.49) 8993.46,6604.49 ccw(c9007.95,6604.49) v3@8997.71,6594.24 ; R52.1@8993.46,6540 R53.1@8993.46,6640 ; v3@9091,7558 cw(c9076.51,7558) 9086.76,7547.76 cw(c9097,7537.51) v3@9097,7552 ; R55.1@9173.46,6540 v3(9234,6540) ; R55.1@9185.11,6530.32 cw(c9208.47,6506.96) 9208.47,6540 cw(c9208.47,6573.04) R55.1@9185.11,6549.68 ; v3(9198,6100) FB5.2@9266.54,6100 ; v3@9202.24,6095.76 cw(c9212.49,6085.51) 9212.49,6100 cw(c9212.49,6114.49) v3@9202.24,6104.24 ; v3@9229.76,6535.76 ccw(c9219.51,6525.51) 9219.51,6540 ccw(c9219.51,6554.49) v3@9229.76,6544.24 ; FB5.2@9254.89,6090.32 ccw(c9231.53,6066.96) 9231.53,6100 ccw(c9231.53,6133.04) FB5.2@9254.89,6109.68 ; v2(9434.04,7085.04) 9434.04,7069.76 9446,7057.8 U16.8@9500,7057.8 ; v2@9437.22,7082.61 ccw(c9447.59,7074.67) 9438.36,7065.44 ; U17.5@9442.36,7725 9518,7725 v2(9555.2,7762.2) 9555.2,7801.74 C37.1@9560,7806.54 ; U17.5@9477.97,7720.89 cw(c9487.89,7710.97) 9487.89,7725 cw(c9487.89,7739.03) U17.5@9477.97,7729.11 ; C37.1@9550.32,7794.89 cw(c9538.54,7783.1) 9555.2,7783.1 ; v2@9555.2,7761.94 cw(c9599.93,7761.94) C37.1@9569.36,7794.58
  TopLayer w20: C11.1@6633.46,8940 v3(6698,8940) ; C11.1@6642.28,8933.15 cw(c6658.81,8916.62) 6658.81,8940 cw(c6658.81,8963.38) C11.1@6642.28,8946.85 ; 6688.43,9264 cw(c6688.43,9224.9) U5.2@6716.08,9252.55 ; U5.2@6697.9,9327 cw(c6697.9,9292.49) U5.2@6728.53,9308.37 ; U5.2@6710.77,9299.17 ccw(c6665,9275.44) v3(6665,9327) U5.2@6726,9327 ; U5.2@6712.14,9289.19 cw(c6666,9318.85) v3(6666,9264) U5.2@6732,9264 ; C15.1@7000,9493.46 7007.46,9486 U7.3@7180,9486 ; C15.1@7006.85,9498.34 ccw(c7036.65,9528.15) v3@7036.65,9486 ; U7.3@7094.39,9475.39 ccw(c7068.79,9449.79) 7068.79,9486 ccw(c7068.79,9522.21) U7.3@7094.39,9496.61 ; C18.1@7272.15,9123.28 ccw(c7255.62,9139.81) 7279,9139.81 ccw(c7302.38,9139.81) C18.1@7285.85,9123.28 ; C18.1@7279,9114.46 v3(7279,9173) ; FB2.2@7313.15,8457.72 cw(c7296.62,8441.19) 7320,8441.19 cw(c7343.38,8441.19) FB2.2@7326.85,8457.72 ; v3(7320,8405) FB2.2@7320,8466.54 ; 8910.91,9143 cw(c8910.91,9097.61) C35.2@8943.01,9129.7 ; 8919.11,9223 cw(c8919.11,9177.28) C35.2@8956.18,9204.04 ; C35.2@8924.57,9143 ccw(c8924.57,9187.7) C35.2@8956.98,9156.92 ; C35.2@8925.4,9223 ccw(c8925.4,9247.91) C35.2@8943.01,9230.3 ; C35.2@8939.97,9192.33 ccw(c8880,9149.04) v3(8880,9223) C35.2@8962,9223 ; C35.2@8942.48,9170.69 cw(c8878.01,9231.9) v3(8878,9143) C35.2@8956,9143
  TopLayer w40: v3(7052.88,8916.12) C13.2@7139,8916.12 ; C14.2@7159,9156.12 v3(7159,9213) ; C17.1@7278.69,8876.43 cw(c7325.16,8876.43) 7292.3,8909.3 ; C17.1@7279,8874.46 7279,8896 v3(7315,8932) U9.2@7429,8932
  BottomLayer w6: C142.2@8862.99,7360 C142.2@8867,7364.01
  BottomLayer w8: C40.2@4840,8222.99 4840,8227 v3(4868,8255) ; C40.2@4840,8236.49 ccw(c4840,8259.41) 4856.2,8243.2 ; C40.2@4851,8225.49 cw(c4881.2,8225.49) v3@4859.84,8246.84 ; v3@4860,8255 cw(c4840.69,8255) 4854.34,8241.34 cw(c4868,8227.69) v3@4868,8247 ; C68.1@5920,8088.88 cw(c5920,8046.26) 5950.14,8076.4 ; C68.1@5920,8096.88 cw(c5920,8073.58) C68.1@5936.48,8090.06 ; C68.1@5920,8106.54 v3(5966.54,8060) ; C68.1@5935.69,8104.57 ccw(c5968.8,8104.57) 5945.38,8081.15 ; v3@5958.54,8060 ccw(c5939.22,8060) 5952.88,8073.66 ccw(c5966.54,8087.31) 5966.54,8068 ccw(c5966.54,8104.04) 5992.02,8078.56 ; 5978.36,8064.9 cw(c5966.54,8076.73) v3(5966.54,8060) ; 5989.86,8076.4 cw(c6020,8046.26) C72.2@6020,8088.88 ; 5994.62,8081.15 ccw(c5971.2,8104.57) C72.2@6004.31,8104.57 ; C72.2@6003.52,8090.06 cw(c6020,8073.58) C72.2@6020,8096.88 ; v3(6007,8300) R67.1@6066.54,8300 ; v3(6007,8420) R68.1@6066.54,8420 ; v3@6012.66,8294.34 cw(c6026.31,8280.69) 6026.31,8300 cw(c6026.31,8319.31) v3@6012.66,8305.66 ; v3@6012.66,8414.34 cw(c6026.31,8400.69) 6026.31,8420 cw(c6026.31,8439.31) v3@6012.66,8425.66 ; C72.2@6020,8106.54 5973.46,8060 v3(5966.54,8060) ; R67.1@6053.48,8288.91 ccw(c6026.7,8262.13) 6026.7,8300 ccw(c6026.7,8337.87) R67.1@6053.48,8311.09 ; R68.1@6053.48,8408.91 ccw(c6026.7,8382.13) 6026.7,8420 ccw(c6026.7,8457.87) R68.1@6053.48,8431.09 ; C76.1@6108.91,8093.48 cw(c6082.13,8066.7) 6120,8066.7 cw(c6157.87,8066.7) C76.1@6131.09,8093.48 ; v3@6114.34,8054.66 ccw(c6100.69,8068.31) 6120,8068.31 ccw(c6139.31,8068.31) v3@6125.66,8054.66 ; v3(6120,8049) C76.1@6120,8106.54 ; C89.1@7880,8413.46 C89.1@7883.46,8416.93 ; C91.2@8000,7717.01 8003.99,7721 v2(8039.63,7721) ; v2(8001,7600) C95.2@8037.01,7600 ; v2(8001.52,7641) 8017.09,7641 C96.2@8036.87,7660.77 ; v2(8002,6813.75) 8018.74,6797.01 ; C93.2@8031.02,6790.65 ccw(c8018.74,6781.96) 8018.74,6797.01 ; C93.2@8031.02,6803.36 cw(c8018.74,6812.05) 8018.74,6797.01 ; C93.2@8040,6797.01 8018.74,6797.01 ; C97.2@8120,7782.99 v2(8120,7799.02) ; C101.2@8140,7442.99 8142.01,7445 v2(8159.68,7445) ; C100.2@8160,7282.99 v2(8160,7327) ; C103.2@8180,7782.99 8193,7795.99 v2(8193,7845) ; C109.2@8240,7782.99 8253.01,7782.99 v2(8277,7759) ; C108.2@8257.01,7640 8257.01,7621.73 v2(8276.34,7602.4) ; v2(8316,6932.82) 8331.81,6917.01 C110.2@8340,6917.01 ; C105.1@8320,7300 8320,7357.01 C107.2@8322.99,7360 ; C116.2@8420,7722.99 8420,7744.69 v2(8435,7759.69) ; C119.2@8440,6919.01 8445.81,6919.01 v2(8472.82,6892) ; v2(8473.79,7641) 8473.79,7670.79 C127.2@8480,7677.01 ; C120.2@8520.99,6919.01 C120.2@8520,6919.01 8546.01,6893 v2(8553.99,6893) C128.2@8580,6919.01 ; C132.2@8540,7742.99 8540,7785.95 v2(8553.41,7799.37) ; C124.2@8562.99,7420 8596,7420 v2(8604,7428) ; C133.2@8620,7760.99 8620,7787.21 v2(8631.67,7798.88) ; C134.2@8680,6877.01 8689.83,6877.01 v2(8711.62,6855.21) ; C139.2@8680,7760.99 8680,7768.47 v2(8709.82,7798.29) ; C140.2@8760,6917.01 8773.42,6917.01 v2(8787.41,6931) ; C144.2@8820,7760.99 8820.99,7760 v2(8868,7760) ; C142.2@8867,7364.01 v2(8867,7405) ; C145.2@8900,7869.49 cw(c8900,7807.91) 8943.54,7851.46 ; C145.2@8900,7877.49 cw(c8900,7835.22) 8929.89,7865.11 ; C145.2@8900,7882.99 8912.01,7882.99 v2(8951,7844) ; C145.2@8900,7885.49 cw(c8900,7862.54) 8916.23,7878.77 ; C146.2@9020,7939 v2(9077,7939) cw(c9077,7965.59) C146.2@9050.91,7960.44 ; C146.2@9034,7975 v2(9069,7975) ; C146.2@9035.22,7957.34 ccw(c9057.53,7961.75) 9057.53,7939 ; C146.2@9043.06,7958.89 ccw(c9067.27,7963.67) v2@9067.27,7939 ; C146.2@9043.38,7935.68 cw(c9051.41,7927.65) C146.2@9051.41,7939 ; v2@9064.76,7970.76 ccw(c9054.51,7960.51) 9054.51,7975 ccw(c9054.51,7989.49) v2@9064.76,7979.24 ; v2@9072.76,7934.76 ccw(c9062.51,7924.51) 9062.51,7939 ccw(c9062.51,7953.49) v2@9072.76,7943.24 ; C147.2@9107.35,6727.95 ccw(c9132.15,6733.39) C147.2@9132.15,6708 ; C147.2@9114,6708 v2(9162,6708) cw(c9162,6739.95) C147.2@9130.79,6733.1 ; C147.2@9115.17,6729.66 ccw(c9142.1,6735.58) 9142.1,6708 ; v2@9117,7891 cw(c9117,7876.51) 9127.24,7886.76 cw(c9137.49,7897) v2@9123,7897 ; v2@9121.24,7892.76 cw(c9138.73,7875.27) 9138.73,7900 ; v2(9122.8,7762.2) U21.41@9185.04,7762.2 ; C147.2@9122.98,6731.38 ccw(c9152.05,6737.76) v2@9152.05,6708 ; v2@9127.04,7757.96 cw(c9137.28,7747.72) 9137.28,7762.2 cw(c9137.28,7776.69) v2@9127.04,7766.45 ; v2@9157.76,6703.76 ccw(c9147.51,6693.51) 9147.51,6708 ccw(c9147.51,6722.49) v2@9157.76,6712.24 ; U20.32@9185.04,7085.04 9238.96,7085.04 9247.2,7076.8 v2(9247.2,7057.8) ; U20.41@9185.04,7262.2 v2(9242.2,7262.2) ; U20.47@9185.04,7380.31 9226.32,7380.31 v2(9246,7400) U20.48@9185.04,7400 ; U21.32@9185.04,7585.04 v2(9240.96,7585.04) ; U21.47@9185.04,7880.31 9133.68,7880.31 v2(9117,7897) 9120,7900 U21.48@9185.04,7900 ; U20.47@9218.9,7381.83 ccw(c9218.9,7403.38) 9234.14,7388.14 ; v2@9236.72,7580.8 ccw(c9226.47,7570.55) 9226.47,7585.04 ccw(c9226.47,7599.53) v2@9236.72,7589.28 ; v2@9237.96,7257.96 ccw(c9227.72,7247.72) 9227.72,7262.2 ccw(c9227.72,7276.69) v2@9237.96,7266.45 ; v2@9240,7400 cw(c9225.51,7400) 9235.76,7389.76 cw(c9246,7379.51) v2@9246,7394 ; v2@9241.76,7395.76 ccw(c9231.51,7385.51) 9231.51,7400 ccw(c9231.51,7414.49) v2@9241.76,7404.24 ; v2@9242.96,7062.04 ccw(c9232.72,7072.28) 9247.2,7072.28 ccw(c9261.69,7072.28) v2@9251.45,7062.04 ; v2@9411.76,7475.24 ccw(c9401.51,7485.49) 9416,7485.49 ccw(c9430.49,7485.49) v2@9420.24,7475.24 ; v2(9416,7471) 9416,7561 9440.04,7585.04 U21.17@9500,7585.04 ; v2(9427.04,7234.96) 9454.28,7262.2 U20.8@9500,7262.2 ; v2@9427.04,7240.96 ccw(c9427.04,7255.45) 9437.28,7245.2 ccw(c9447.53,7234.96) v2@9433.04,7234.96 ; v2(9434.04,7085.04) U20.17@9500,7085.04 ; v2@9438.28,7080.8 cw(c9448.53,7070.55) 9448.53,7085.04 cw(c9448.53,7099.53) v2@9438.28,7089.28 ; U21.8@9500,7762.2 v2(9555.2,7762.2) ; v2@9550.96,7757.96 ccw(c9540.72,7747.72) 9540.72,7762.2 ccw(c9540.72,7776.69) v2@9550.96,7766.45
  BottomLayer w10: C104.2@8277,7222 v2(8333,7222) 8335,7220 C112.1@8378,7220 ; C106.2@8282,7412 v2(8334,7412) ; C106.2@8284,7439 v2(8335,7439) ; C104.2@8285,7251 v2(8334,7251) ; C111.2@8380,7162.99 8382,7160.99 C122.2@8440,7160.99 ; C115.2@8380,7477.01 C126.2@8440,7477.01 ; C121.2@8500,7160.99 8502,7162.99 C129.2@8560,7162.99 ; C125.2@8500,7477.01 C131.2@8560,7477.01 ; v2(8549.37,7290) 8570,7290 C130.1@8580,7300 ; v2(8604,7428) C138.2@8660,7428 ; v2(8605,7464) C138.2@8659,7464 ; C136.2@8637.01,7300 C137.2@8637.01,7360 ; C135.2@8644,7220 v2(8644,7259) ; C135.2@8674,7222 v2(8674,7258) ; v2(8749.56,7090) 8762.55,7077.01 C141.2@8780,7077.01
